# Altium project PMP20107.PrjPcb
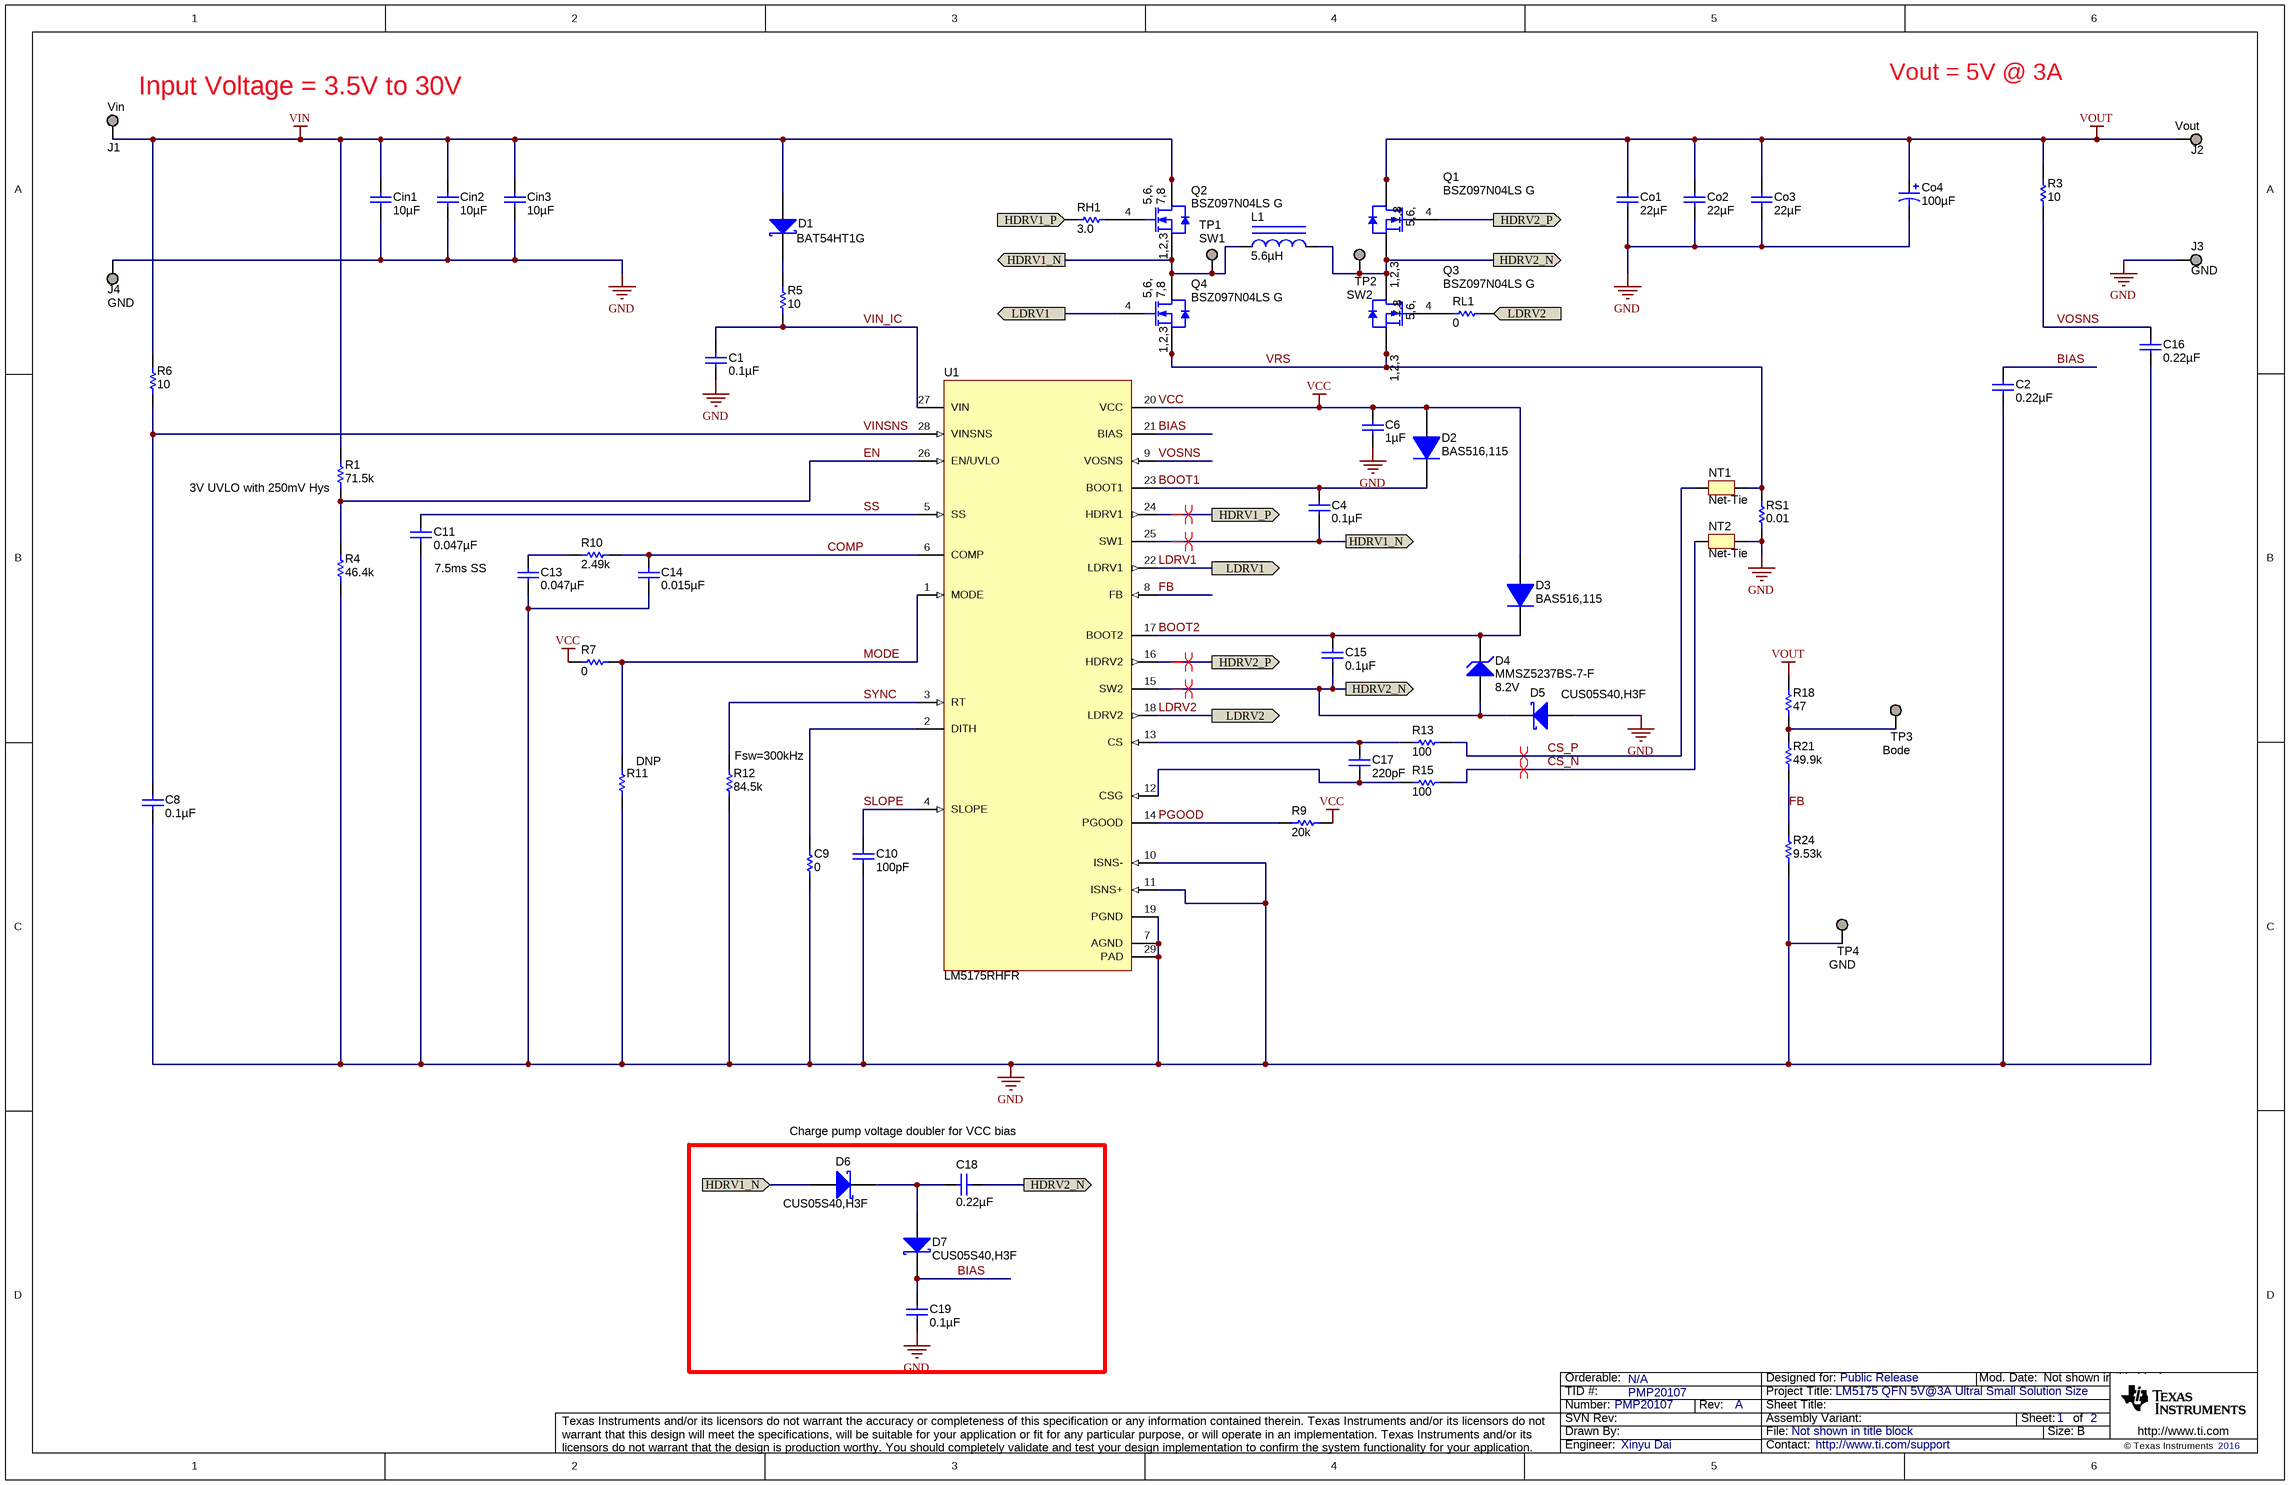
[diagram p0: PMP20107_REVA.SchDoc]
CopyrightYear: 2016; EVM_Orderable: N/A; PCB_Layout: Xinyu Dai; PCB_Rev: A; PRJ_Customer: Public Release; PRJ_Engineer: Xinyu Dai; PRJ_Number: PMP20107; PRJ_Title: LM5175 QFN 5V@3A Ultral Small Solution Size; SCH_Rev: A; TechSupport: http://www.ti.com/support; TID: PMP20107
2 sheets, 71 parts. Net scope: flat (ports and power ports of the same name join across sheets).
Board file: PMP20107_REVA.PcbDoc
Sheets:
  PMP20107_REVA.SchDoc
  PMP20107_REVA_Hardware.SchDoc

## Sheet PMP20107_REVA.SchDoc
size 431 x 279 mm; Date: Not shown in title block; ApprovedBy: Not shown in title block; CheckedBy: Not shown in title block; Author: Not shown in title block; CompanyName: Not shown in title block; Engineer: Not shown in title block; Organization: Not shown in title block; Address1: Not shown in title block; Address2: Not shown in title block; Address3: Not shown in title block; Address4: Not shown in title block; DocumentNumber: 1; Revision: Use project parameter SCH_Rev; SheetNumber: 1; SheetTotal: 2; PageSetup: Record=PageOptions¦CenterHorizontal=True¦CenterVertical=True¦PrintScale=1.00¦XCorrection=1.00¦YCorrection=1.00¦PrintKind=0¦BorderSize=5000000¦LeftOffset=0¦BottomOffset=0¦Orientation=2¦PaperLength=1000¦PaperWidth=1000¦Scale=100¦PaperSource=15¦PrintQuality=600¦MediaType=1¦DitherType=10¦PaperKind=Letter¦PrintScaleMode=1

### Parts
C1  ValueDisplayed: 0.1µF  [0402L]  (hidden comment: GCM155R71H104KE02D)
C2  ValueDisplayed: 0.22µF  [0402L]  (hidden comment: C1005X5R1E224M050BC)
C4  ValueDisplayed: 0.1µF  [0402L]  (hidden comment: GCM155R71H104KE02D)
C6  ValueDisplayed: 1µF  [0402L]  (hidden comment: C1005X5R1C105K050BC)
C8  ValueDisplayed: 0.1µF  [0402L]  (hidden comment: GCM155R71H104KE02D)
C9  ValueDisplayed: 0  [0402L]  (hidden comment: CRCW04020000Z0ED)
C10  ValueDisplayed: 100pF  [0402L]  (hidden comment: CC0402KRX7R9BB101)
C11  ValueDisplayed: 0.047µF  [0402L]  (hidden comment: C1005X7R1H473K050BB)
C13  ValueDisplayed: 0.047µF  [0402L]  (hidden comment: GRM155R71E473KA88D)
C14  ValueDisplayed: 0.015µF  [0402L]  (hidden comment: GRM155R71E153KA61D)
C15  ValueDisplayed: 0.1µF  [0402L]  (hidden comment: GCM155R71H104KE02D)
C16  ValueDisplayed: 0.22µF  [0402L]  (hidden comment: C1005X5R1E224M050BC)
C17  ValueDisplayed: 220pF  [0402L]  (hidden comment: C1005X7R1H221K)
C18  ValueDisplayed: 0.22µF  [0402L]  (hidden comment: C1005X5R1E224M050BC)
C19  ValueDisplayed: 0.1µF  [0402L]  (hidden comment: GCM155R71H104KE02D)
Cin1  ValueDisplayed: 10µF  [1206_190]  (hidden comment: C3216X7R1V106M160AC)
Cin2  ValueDisplayed: 10µF  [1206_190]  (hidden comment: C3216X7R1V106M160AC)
Cin3  ValueDisplayed: 10µF  [1206_190]  (hidden comment: C3216X7R1V106M160AC)
Co1  ValueDisplayed: 22µF  [1206_190]  (hidden comment: GRM31CR71A226ME15L)
Co2  ValueDisplayed: 22µF  [1206_190]  (hidden comment: GRM31CR71A226ME15L)
Co3  ValueDisplayed: 22µF  [1206_190]  (hidden comment: GRM31CR71A226ME15L)
Co4  ValueDisplayed: 100µF  [SM_RADIAL_6.3AMM]  (hidden comment: UUD1A101MCL1GS)
D1  BAT54HT1G  [sod-323]
D2  BAS516,115  [SOD-523]
D3  BAS516,115  [SOD-523]
D4  MMSZ5237BS-7-F  value 8.2V  [sod-323]
D5  CUS05S40,H3F  [sod-323]
D6  CUS05S40,H3F  [sod-323]
D7  CUS05S40,H3F  [sod-323]
J1  Vin  [Keystone_5019]  (no BOM)
J2  Vout  [Keystone_5019]  (no BOM)
J3  GND  [Keystone_5019]  (no BOM)
J4  GND  [Keystone_5019]  (no BOM)
L1  ValueDisplayed: 5.6µH  [XAL5050]  (hidden comment: XAL5050-562MEB)
NT1  Net-Tie  [Net-Tie_10mil]  (net tie, no BOM)
NT2  Net-Tie  [Net-Tie_10mil]  (net tie, no BOM)
Q1  BSZ097N04LS G  [PG-TSDSON-8]
Q2  BSZ097N04LS G  [PG-TSDSON-8]
Q3  BSZ097N04LS G  [PG-TSDSON-8]
Q4  BSZ097N04LS G  [PG-TSDSON-8]
R1  ValueDisplayed: 71.5k  [0402L]  (hidden comment: CRCW040271K5FKED)
R3  ValueDisplayed: 10  [0402L]  (hidden comment: CRCW040210R0JNED)
R4  ValueDisplayed: 46.4k  [0402L]  (hidden comment: CRCW040246K4FKED)
R5  ValueDisplayed: 10  [0402L]  (hidden comment: CRCW040210R0JNED)
R6  ValueDisplayed: 10  [0402L]  (hidden comment: CRCW040210R0JNED)
R7  ValueDisplayed: 0  [0402L]  (hidden comment: CRCW04020000Z0ED)
R9  ValueDisplayed: 20k  [0402L]  (hidden comment: CRCW040220K0JNED)
R10  ValueDisplayed: 2.49k  [0402L]  (hidden comment: CRCW04022K49FKED)
R11  DNP  [0402L]
R12  ValueDisplayed: 84.5k  [0402L]  (hidden comment: CRCW040284K5FKED)
R13  ValueDisplayed: 100  [0402L]  (hidden comment: CRCW0402100RFKED)
R15  ValueDisplayed: 100  [0402L]  (hidden comment: CRCW0402100RFKED)
R18  ValueDisplayed: 47  [0402L]  (hidden comment: CRCW040247R0JNED)
R21  ValueDisplayed: 49.9k  [0402L]  (hidden comment: CRCW040249K9FKED)
R24  ValueDisplayed: 9.53k  [0402L]  (hidden comment: CRCW04029K53FKED)
RH1  ValueDisplayed: 3.0  [0402L]  (hidden comment: CRCW04023R00JNED)
RL1  ValueDisplayed: 0  [0402L]  (hidden comment: CRCW04020000Z0ED)
RS1  ValueDisplayed: 0.01  [0612]  (hidden comment: ERJ-B2CFR01V)
TP1  SW1  [Keystone_5019]  (no BOM)
TP2  SW2  [Keystone_5019]  (no BOM)
TP3  Bode  [Keystone_5019]  (no BOM)
TP4  GND  [Keystone_5019]  (no BOM)
U1  LM5175RHFR  [RHF0028A]

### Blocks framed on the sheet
Charge pump voltage doubler for VCC bias: C18 C19 D6 D7

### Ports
HDRV1_N, HDRV1_P (out), HDRV2_N, HDRV2_P (out), LDRV1 (out), LDRV2 (out)

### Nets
GND: C1.2 C2.2 C6.2 C8.1 C9.2 C10.2 C11.2 C13.2 C14.2 C16.2 C19.2 Cin1.2 Cin2.2 Cin3.2 Co1.2 Co2.2 Co3.2 Co4.2(-) D5.2(A) J3.1 J4.1 NT2.1 R4.1 R11.1 R12.1 R24.1 RS1.1 TP4.1 U1.7(AGND) U1.10(ISNS-) U1.11(ISNS+) U1.19(PGND) U1.29(PAD)
VCC: C6.1 D2.2(A) D3.2(A) R7.2 R9.2 U1.20(VCC)
VIN: Cin1.1 Cin2.1 Cin3.1 D1.2(A) J1.1 Q2.5(D) Q2.6(D) Q2.7(D) Q2.8(D) Q2.9(D) R1.2 R6.1
VOUT: Co1.1 Co2.1 Co3.1 Co4.1(+) J2.1 Q1.5(D) Q1.6(D) Q1.7(D) Q1.8(D) Q1.9(D) R3.2 R18.1
BIAS: C2.1 C19.1 D7.1(K) U1.21(BIAS)
BOOT1: C4.1 D2.1(K) U1.23(BOOT1)
BOOT2: C15.2 D3.1(K) D4.1(K) U1.17(BOOT2)
COMP: C14.1 R10.2 U1.6(COMP)
CS_N: NT2.2 R15.2
CS_P: NT1.2 R13.2
EN: R1.1 R4.2 U1.26(EN/UVLO)
FB: R21.1 R24.2 U1.8(FB)
HDRV1_N: C4.2 D6.2(A) L1.1 Q2.1(S) Q2.2(S) Q2.3(S) Q4.5(D) Q4.6(D) Q4.7(D) Q4.8(D) Q4.9(D) TP1.1 U1.25(SW1) ; port HDRV1_N
HDRV1_P: RH1.1 U1.24(HDRV1) ; port HDRV1_P
HDRV2_N: C15.1 C18.2 D4.2(A) D5.1(K) L1.2 Q1.1(S) Q1.2(S) Q1.3(S) Q3.5(D) Q3.6(D) Q3.7(D) Q3.8(D) Q3.9(D) TP2.1 U1.15(SW2) ; port HDRV2_N
HDRV2_P: Q1.4(G) U1.16(HDRV2) ; port HDRV2_P
LDRV1: Q4.4(G) U1.22(LDRV1) ; port LDRV1
LDRV2: RL1.2 U1.18(LDRV2) ; port LDRV2
MODE: R7.1 R11.2 U1.1(MODE)
PGOOD: R9.1 U1.14(PGOOD)
SLOPE: C10.1 U1.4(SLOPE)
SS: C11.1 U1.5(SS)
SYNC: R12.2 U1.3(RT)
VIN_IC: C1.1 R5.1 U1.27(VIN)
VINSNS: C8.2 R6.2 U1.28(VINSNS)
VOSNS: C16.1 R3.1 U1.9(VOSNS)
VRS: NT1.1 Q3.1(S) Q3.2(S) Q3.3(S) Q4.1(S) Q4.2(S) Q4.3(S) RS1.2
NetC9_1: C9.1 U1.2(DITH)
NetC13_1: C13.1 R10.1
NetC17_1: C17.1 R13.1 U1.13(CS)
NetC17_2: C17.2 R15.1 U1.12(CSG)
NetC18_1: C18.1 D6.1(K) D7.2(A)
NetD1_1: D1.1(K) R5.2
NetQ2_4: Q2.4(G) RH1.2
NetQ3_4: Q3.4(G) RL1.1
NetR18_2: R18.2 R21.2 TP3.1

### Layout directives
differential pair: CS_N, CS_P, HDRV1_N, HDRV1_P, HDRV2_N, HDRV2_P

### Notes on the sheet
- (near J1) Input Voltage = 3.5V to 30V
- Vout = 5V @ 3A
- (near R1) 3V UVLO with 250mV Hys
- (near C11) 7.5ms SS
- (near R12) Fsw=300kHz

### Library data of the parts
C1 C4 C8 C15 C19 = GCM155R71H104KE02D: CAP, CERM, 0.1 µF, 50 V, +/- 10%, X7R, AEC-Q200 Grade 1, 0402; Manufacturer: MuRata; Polarized: N; CompType: Capacitor; Value: 0.1uF; U/M: EA; Cap_F: 0.0000001; Tolerance_%: 10; Value1: Unknown; VDC_V: 50; Value2: 50V; TaMin_C: -55; TaMax_C: 125; Cap_Case: 0402; AEC Category: Q200; AEC Qualified: Y; AEC Grade: 1
C2 C16 C18 = C1005X5R1E224M050BC: CAP, CERM, 0.22 µF, 25 V, +/- 20%, X5R, 0402; Manufacturer: TDK; Polarized: N; CompType: Capacitor; Value: 0.22uF; U/M: EA; Cap_F: 0.00000022; Tolerance_%: 20; Value1: Unknown; VDC_V: 25; Value2: 25V; TaMin_C: -55; TaMax_C: 85; Cap_Case: 0402; AEC Category: Q200
C6 = C1005X5R1C105K050BC: CAP, CERM, 1 µF, 16 V, +/- 10%, X5R, 0402; Manufacturer: TDK; Polarized: N; CompType: Capacitor; Value: 1uF; U/M: EA; Cap_F: 0.000001; Tolerance_%: 10; Value1: Unknown; VDC_V: 16; Value2: 16V; TaMin_C: -55; TaMax_C: 85; Cap_Case: 0402; AEC Category: Q200
C9 R7 RL1 = CRCW04020000Z0ED: RES, 0, 5%, 0.063 W, 0402; Manufacturer: Vishay-Dale; CompType: Resistor; Value: 0; Value_Code: 0000; Tolerance_%: 5; Power_W: 0.063; Value2: 0.063W; VDC_V: 50; TempCo: 200 ppm/C; EIA_Code: E24; U/M: EA; AEC Category: Q200
C10 = CC0402KRX7R9BB101: CAP, CERM, 100 pF, 50 V, +/- 10%, X7R, 0402; Manufacturer: Yageo America; Polarized: N; CompType: Capacitor; Value: 100pF; U/M: EA; Cap_F: 0.0000000001; Tolerance_%: 10; Value1: Unknown; VDC_V: 50; Value2: 50V; TaMin_C: -55; TaMax_C: 125; Cap_Case: 0402; AEC Category: Q200
C11 = C1005X7R1H473K050BB: CAP, CERM, 0.047 µF, 50 V, +/- 10%, X7R, 0402; Manufacturer: TDK; Polarized: N; CompType: Capacitor; Value: 0.047uF; U/M: EA; Cap_F: 0.000000047; Tolerance_%: 10; Value1: Unknown; VDC_V: 50; Value2: 50V; TaMin_C: -55; TaMax_C: 125; Cap_Case: 0402; AEC Category: Q200
C13 = GRM155R71E473KA88D: CAP, CERM, 0.047 µF, 25 V, +/- 10%, X7R, 0402; Manufacturer: MuRata; Polarized: N; CompType: Capacitor; Value: 0.047uF; U/M: EA; Cap_F: 0.000000047; Tolerance_%: 10; Value1: Unknown; VDC_V: 25; Value2: 25V; TaMin_C: -55; TaMax_C: 125; Cap_Case: 0402; AEC Category: Q200
C14 = GRM155R71E153KA61D: CAP, CERM, 0.015 µF, 25 V, +/- 10%, X7R, 0402; Manufacturer: MuRata; Polarized: N; CompType: Capacitor; Value: 0.015uF; U/M: EA; Cap_F: 0.000000015; Tolerance_%: 10; Value1: Unknown; VDC_V: 25; Value2: 25V; TaMin_C: -55; TaMax_C: 125; Cap_Case: 0402; AEC Category: Q200
C17 = C1005X7R1H221K: CAP, CERM, 220 pF, 50 V, +/- 10%, X7R, 0402; Manufacturer: TDK; Polarized: N; CompType: Capacitor; Value: 220pF; U/M: EA; Cap_F: 0.00000000022; Tolerance_%: 10; ESR_ohm: 0.59; Value1: 0.59 ohm; VDC_V: 50; Value2: 50V; TaMin_C: -55; TaMax_C: 125; Cap_Case: 0402; AEC Category: Q200
Cin1-Cin3 = C3216X7R1V106M160AC: CAP, CERM, 10 µF, 35 V, +/- 20%, X7R, 1206_190; Manufacturer: TDK; Polarized: N; CompType: Capacitor; Value: 10uF; U/M: EA; Cap_F: 0.00001; Tolerance_%: 20; Value1: Unknown; VDC_V: 35; Value2: 35V; TaMin_C: -55; TaMax_C: 125; Cap_Case: 1206; AEC Category: Q200
Co1-Co3 = GRM31CR71A226ME15L: CAP, CERM, 22 µF, 10 V, +/- 20%, X7R, 1206_190; Manufacturer: MuRata; Polarized: N; CompType: Capacitor; Value: 22uF; U/M: EA; Cap_F: 0.000022; Tolerance_%: 20; Value1: Unknown; VDC_V: 10; Value2: 10V; TaMin_C: -55; TaMax_C: 125; Cap_Case: 1206; AEC Category: Q200
Co4 = UUD1A101MCL1GS: CAP, AL, 100 µF, 10 V, +/- 20%, 0.44 ohm, SMD; Manufacturer: Nichicon; Polarized: Y; CompType: Capacitor; Value: 100uF; U/M: EA; Cap_F: 0.0001; Tolerance_%: 20; VDC_V: 10; Value2: 10V; ESR_ohm: 0.44; IRMS_A: 0.23; TaMin_C: -55; TaMax_C: 105; Cap_Case: 6.3x5.8; AEC Category: Q200
D1 = BAT54HT1G: Diode, Schottky, 30V, 0.2A, SOD-323; Manufacturer: ON Semiconductor; U/M: EA; Vf_V: 0.35; Value2: 0.35V; Io_A: 0.2; Vr_V: 30
D2 D3 = BAS516,115: Diode, Switching, 100V, 0.25A, SOD-523; Manufacturer: NXP Semiconductor; U/M: EA; Vf_V: 1.25; Value2: 1.25V; Io_A: 0.25; Vr_V: 100; TJmax_C: 150
D4 = MMSZ5237BS-7-F: Diode, Zener, 8.2 V, 200 mW, SOD-323; Manufacturer: Diodes Inc.; SymbolCreator: a0412235; U/M: EA; Power_W: 0.2; Vz_V: 8.2; Value1: 0.2W; RJA_CperW: 350; AEC Category: Q101
D5-D7 = CUS05S40,H3F: Diode, Schottky, 40 V, 0.5 A, SOD-323; Manufacturer: Toshiba; U/M: EA; Vf_V: 0.6; Value: 40V; Value1: 0.5A; Value2: 0.6V; Io_A: 0.5; Vr_V: 40; TJmax_C: 125; AEC Category: Q101; AEC Qualified: N
J1-J4 TP1-TP4 = 5019: Test Point, Miniature, SMT; Manufacturer: Keystone; CompType: Test Point Loop
L1 = XAL5050-562MEB: Inductor, Shielded, Composite, 5.6 µH, 6.3 A, 0.03 ohm, SMD; Manufacturer: Coilcraft; Value: 5.6uH; Ind_H: 5.6E-6; Imax_A: 6.3; Irms: 7.2A @ 40C rise; Isat: 6.3A @ 30% inductance drop; DCR_ohm: 0.03; Value2: 6.3A; AEC Category: Q200
NT1 NT2 = Net-Tie: Single point connection between nets.; SymbolCreator: codlsc
Q1-Q4 = BSZ097N04LS G: MOSFET, N-CH, 40 V, 40 A, PG-TSDSON-8; Manufacturer: Infineon Technologies; Alternate Manufacturer: None; U/M: EA; ChType: N; Value: 40V; VdsMax_V: 40; Value1: 0.0142 ohm; Rdson45_ohm: 0.0142; Value2: 8.6 nC; QgTyp_nC: 8.6; Vgs_V: 20; AEC Category: Q101
R1 = CRCW040271K5FKED: RES, 71.5 k, 1%, 0.063 W, 0402; Manufacturer: Vishay-Dale; CompType: Resistor; Value: 71.5k; Res_ohm: 71500; Value_Code: 71k5; Tolerance_%: 1; Power_W: 0.063; Value2: 0.063W; VDC_V: 50; TempCo: 100 ppm/C; EIA_Code: E96; U/M: EA; AEC Category: Q200
R3 = CRCW040210R0JNED: RES, 10, 5%, 0.063 W, 0402; Manufacturer: Vishay-Dale; CompType: Resistor; Value_Code: 10R0; Tolerance_%: 5; Power_W: 0.063; Value2: 0.063W; VDC_V: 50; TempCo: 200 ppm/C; EIA_Code: E24; U/M: EA; Value: 10; AEC Category: Q200
R4 = CRCW040246K4FKED: RES, 46.4 k, 1%, 0.063 W, 0402; Manufacturer: Vishay-Dale; CompType: Resistor; Value: 46.4k; Res_ohm: 46400; Value_Code: 46k4; Tolerance_%: 1; Power_W: 0.063; Value2: 0.063W; VDC_V: 50; TempCo: 100 ppm/C; EIA_Code: E96; U/M: EA; AEC Category: Q200
R5 = CRCW040210R0JNED: RES, 10, 5%, 0.063 W, 0402; Manufacturer: Vishay-Dale; CompType: Resistor; Value: 10; Value_Code: 10R0; Tolerance_%: 5; Power_W: 0.063; Value2: 0.063W; VDC_V: 50; TempCo: 200 ppm/C; SizeArea_mm2: 0.5; SizeX_mm: 1; SizeZ_mm: 0.6; EIA_Code: E24; U/M: EA; AEC Category: Q200
R6 = CRCW040210R0JNED: RES, 10, 5%, 0.063 W, 0402; Manufacturer: Vishay-Dale; CompType: Resistor; Value: 10; Value_Code: 10R0; Tolerance_%: 5; Power_W: 0.063; Value2: 0.063W; VDC_V: 50; TempCo: 200 ppm/C; EIA_Code: E24; U/M: EA; AEC Category: Q200
R9 = CRCW040220K0JNED: RES, 20 k, 5%, 0.063 W, 0402; Manufacturer: Vishay-Dale; CompType: Resistor; Value: 20k; Res_ohm: 20000; Value_Code: 20k0; Tolerance_%: 5; Power_W: 0.063; Value2: 0.063W; VDC_V: 50; TempCo: 200 ppm/C; EIA_Code: E24; U/M: EA; AEC Category: Q200
R10 = CRCW04022K49FKED: RES, 2.49 k, 1%, 0.063 W, 0402; Manufacturer: Vishay-Dale; CompType: Resistor; Res_ohm: 2490; Value_Code: 2k49; Tolerance_%: 1; Power_W: 0.063; Value2: 0.063W; VDC_V: 50; TempCo: 100 ppm/C; EIA_Code: E96; U/M: EA; Value: 2.49k; AEC Category: Q200
R11 = CRCW040295K3FKED: RES, 95.3 k, 1%, 0.063 W, 0402; Manufacturer: Vishay-Dale; CompType: Resistor; Value: 95.3k; Res_ohm: 95300; Value_Code: 95k3; Tolerance_%: 1; Power_W: 0.063; Value2: 0.063W; VDC_V: 50; TempCo: 100 ppm/C; EIA_Code: E96; U/M: EA; AEC Category: Q200
R12 = CRCW040284K5FKED: RES, 84.5 k, 1%, 0.063 W, 0402; Manufacturer: Vishay-Dale; CompType: Resistor; Value: 84.5k; Res_ohm: 84500; Value_Code: 84k5; Tolerance_%: 1; Power_W: 0.063; Value2: 0.063W; VDC_V: 50; TempCo: 100 ppm/C; EIA_Code: E96; U/M: EA; AEC Category: Q200
R13 R15 = CRCW0402100RFKED: RES, 100, 1%, 0.063 W, 0402; Manufacturer: Vishay-Dale; CompType: Resistor; Value: 100; Value_Code: 100R; Tolerance_%: 1; Power_W: 0.063; Value2: 0.063W; VDC_V: 50; TempCo: 100 ppm/C; EIA_Code: E96; U/M: EA; AEC Category: Q200
R18 = CRCW040247R0JNED: RES, 47, 5%, 0.063 W, 0402; Manufacturer: Vishay-Dale; CompType: Resistor; Value: 47; Value_Code: 47R0; Tolerance_%: 5; Power_W: 0.063; Value2: 0.063W; VDC_V: 50; TempCo: 200 ppm/C; EIA_Code: E24; U/M: EA; AEC Category: Q200
R21 = CRCW040249K9FKED: RES, 49.9 k, 1%, 0.063 W, 0402; Manufacturer: Vishay-Dale; CompType: Resistor; Value: 49.9k; Res_ohm: 49900; Value_Code: 49k9; Tolerance_%: 1; Power_W: 0.063; Value2: 0.063W; VDC_V: 50; TempCo: 100 ppm/C; EIA_Code: E96; U/M: EA; AEC Category: Q200
R24 = CRCW04029K53FKED: RES, 9.53 k, 1%, 0.063 W, 0402; Manufacturer: Vishay-Dale; CompType: Resistor; Value: 9.53k; Res_ohm: 9530; Value_Code: 9k53; Tolerance_%: 1; Power_W: 0.063; Value2: 0.063W; VDC_V: 50; TempCo: 100 ppm/C; EIA_Code: E96; U/M: EA; AEC Category: Q200
RH1 = CRCW04023R00JNED: RES, 3.0, 5%, 0.063 W, 0402; Manufacturer: Vishay-Dale; CompType: Resistor; Value: 3.0; Res_ohm: 3; Value_Code: 3R00; Tolerance_%: 5; Power_W: 0.063; Value2: 0.063W; VDC_V: 50; TempCo: 200 ppm/C; EIA_Code: E24; U/M: EA; AEC Category: Q200
RS1 = ERJ-B2CFR01V: RES, 0.01, 1%, 1 W, AEC-Q200 Grade 0, 0612; Manufacturer: Panasonic; CompType: Resistor; Value: 0.01; Tolerance_%: 1; TempCo: 300 ppm/C; U/M: EA; Value_Code: R010; Value2: 1W; EIA_Code: E96; AEC Category: Q200; AEC Qualified: Y; AEC Grade: 0
U1 = LM5175RHFR: 42-V Wide VIN Synchronous 4-Switch Buck-Boost Controller, RHF0028A; Alternate PartNumber: LM5175RHFT; Manufacturer: Texas Instruments; SymbolCreator: Altium; CompType: IC; U/M: EA

## Sheet PMP20107_REVA_Hardware.SchDoc
size 431 x 279 mm; Date: Not shown in title block; ApprovedBy: Not shown in title block; CheckedBy: Not shown in title block; Author: Not shown in title block; CompanyName: Not shown in title block; Engineer: Not shown in title block; Organization: Not shown in title block; Address1: Not shown in title block; Address2: Not shown in title block; Address3: Not shown in title block; Address4: Not shown in title block; DocumentNumber: 2; Revision: Use project parameter SCH_Rev; SheetNumber: 2; SheetTotal: 2; PageSetup: Record=PageOptions¦CenterHorizontal=True¦CenterVertical=True¦PrintScale=1.00¦XCorrection=1.00¦YCorrection=1.00¦PrintKind=0¦BorderSize=5000000¦LeftOffset=0¦BottomOffset=0¦Orientation=2¦PaperLength=1000¦PaperWidth=1000¦Scale=100¦PaperSource=15¦PrintQuality=600¦MediaType=1¦DitherType=10¦PaperKind=Letter¦PrintScaleMode=1
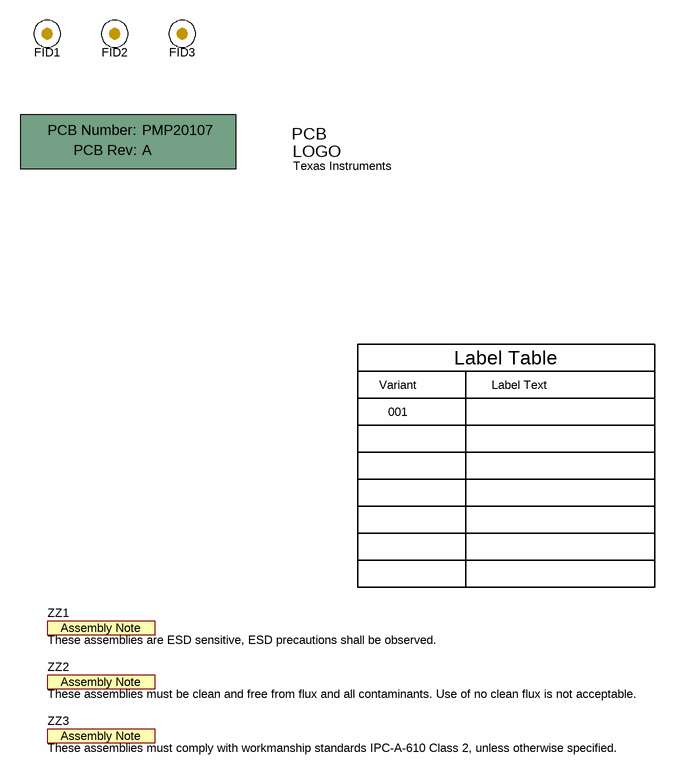
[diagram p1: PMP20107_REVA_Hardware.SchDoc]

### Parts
!PCB1  Printed Circuit Board  (value not drawn)  (mechanical)
FID1  Fiducial  [Fiducial10-20]  (value not drawn)
FID2  Fiducial  [Fiducial10-20]  (value not drawn)
FID3  Fiducial  [Fiducial10-20]  (value not drawn)
Logo1  Texas Instruments  [TI_Stacked_Overlay_Small]  (no BOM)
ZZ1  These assemblies are ESD sensitive, ESD precautions shall be observed.  [AssemblyNote]  (no BOM)
ZZ2  These assemblies must be clean and free from flux and all contaminants. Use of no clean flux is not acceptable.  [AssemblyNote]  (no BOM)
ZZ3  These assemblies must comply with workmanship standards IPC-A-610 Class 2, unless otherwise specified.  [AssemblyNote]  (no BOM)

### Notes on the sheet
- Variant
- Label Table
- Label Text
- 001

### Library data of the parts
!PCB1 = PCB: Manufacturer: Any; PartNumber: PMP20107; SymbolCreator: a0412235
FID1-FID3 = Fiducial: Fiducial mark.  There is nothing to buy or mount.; SymbolCreator: codlsc
Logo1 = TI_Logo: Texas Instrument Corporate Signature; SymbolCreator: codlsc
ZZ1-ZZ3 = AssemblyNote: SymbolCreator: codlsc

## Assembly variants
001: not fitted D4 D5 FID1 FID2 FID3 R11
000: not fitted D4 D5 FID1 FID2 FID3 R11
